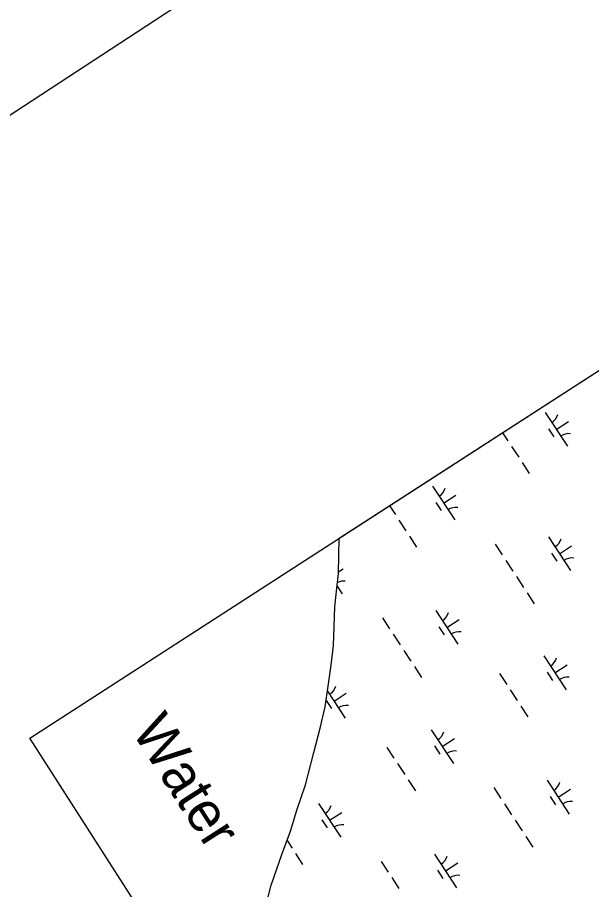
# Model space of a CAD drawing. Extents: x 3945642 to 3966284, y 206476 to 228921.
# Drawn here: x 3949497 to 3950206, y 221813 to 222891 of the extents above; entities that cross this region are included whole.
import ezdxf

# ---------------------------------------------------------------- set-up
doc = ezdxf.new("R2010")
doc.units = 0
for name, color, linetype in [('V-ANNO-SYMB', 7, 'Continuous'), ('V-GRID-FRAM', 7, 'Continuous'), ('V-RIVR-IDEN', 7, 'Continuous'), ('V-TOPO-SHOR', 7, 'Continuous'), ('V-WETL-SWMP', 7, 'Continuous')]:
    doc.layers.add(name, color=color, linetype=linetype)

msp = doc.modelspace()

# ---------------------------------------------------------------- linework, layer by layer
at = {"layer": 'V-ANNO-SYMB'}
msp.add_lwpolyline([(3946901.3, 221076.1), (3955966, 207239.3), (3965550.7, 213518.4), (3956486, 227355.2), (3946901.3, 221076.1)], dxfattribs=at)
at = {"layer": 'V-GRID-FRAM'}
msp.add_lwpolyline([(3956475, 226502.1), (3964764.2, 213849), (3957669.1, 209282.6), (3949512, 222000.5), (3956475, 226502.1)], dxfattribs=at)
at = {"layer": 'V-TOPO-SHOR'}
msp.add_lwpolyline([(3949756.7, 221619.1), (3949761.5, 221632.2), (3949773.3, 221669.4), (3949781.4, 221704.3), (3949790.5, 221741.6), (3949810.1, 221818.6), (3949823.1, 221856.7), (3949834.1, 221885.6), (3949842, 221911.4), (3949852.3, 221942.6), (3949862.9, 221982.7), (3949870.6, 222012.9), (3949876.7, 222039.2), (3949880.7, 222064.7), (3949884.4, 222090.5), (3949886.9, 222114.9), (3949888, 222138.6), (3949888.9, 222162.8), (3949891.4, 222185.7), (3949893.4, 222203.9), (3949894.2, 222247.6)], dxfattribs=at)
at = {"layer": 'V-WETL-SWMP'}
for p, q in [((3949894.2, 222247.6), (3951367.7, 223200.2)), ((3950148.5, 222403.1), (3950175.9, 222361.3)), ((3950152.5, 222383), (3950159.1, 222373)), ((3950162.2, 222382.2), (3950177.3, 222392.1)), ((3950096, 222378), (3950102.6, 222367.9)), ((3950107, 222361.2), (3950115.8, 222347.8)), ((3950120.1, 222341.2), (3950128.9, 222327.8)), ((3950009.4, 222312), (3950036.8, 222270.2)), ((3950023.1, 222291.1), (3950038.1, 222300.9)), ((3949956.3, 222287.7), (3949963.5, 222276.8)), ((3950013.3, 222291.9), (3950019.9, 222281.8)), ((3949967.9, 222270.1), (3949976.6, 222256.7)), ((3949893.4, 222203.9), (3949894.2, 222247.6)), ((3949981, 222250), (3949989.8, 222236.6)), ((3950152.5, 222249.4), (3950179.9, 222207.6)), ((3950086.7, 222240.3), (3950095.4, 222226.9)), ((3950166.2, 222228.5), (3950181.2, 222238.4)), ((3950156.4, 222229.3), (3950163, 222219.3)), ((3950099.8, 222220.2), (3950108.6, 222206.9)), ((3949891.4, 222185.7), (3949893.4, 222203.9)), ((3949893.4, 222206.1), (3949899, 222209.8)), ((3950113, 222200.2), (3950121.7, 222186.8)), ((3949888.9, 222162.8), (3949891.4, 222185.7)), ((3949891.7, 222188.2), (3949897.7, 222179)), ((3950126.1, 222180.1), (3950134.9, 222166.7)), ((3949888, 222138.6), (3949888.9, 222162.8)), ((3950013.3, 222158.3), (3950040.7, 222116.5)), ((3949947.5, 222149.2), (3949956.3, 222135.8)), ((3950027, 222137.4), (3950042.1, 222147.2)), ((3949886.9, 222114.9), (3949888, 222138.6)), ((3950017.3, 222138.2), (3950023.9, 222128.1)), ((3949960.7, 222129.1), (3949969.5, 222115.7)), ((3949884.4, 222090.5), (3949886.9, 222114.9)), ((3949973.8, 222109), (3949982.6, 222095.6)), ((3950146.9, 222102.1), (3950174.3, 222060.2)), ((3949880.7, 222064.7), (3949884.4, 222090.5)), ((3949987, 222088.9), (3949995.8, 222075.6)), ((3950150.9, 222081.9), (3950157.4, 222071.9)), ((3950160.6, 222081.2), (3950175.7, 222091)), ((3950092.2, 222080.2), (3950101, 222066.8)), ((3949876.7, 222039.2), (3949880.7, 222064.7)), ((3950105.4, 222060.2), (3950114.1, 222046.8)), ((3949879.7, 222058.7), (3949901.6, 222025.3)), ((3949887.9, 222046.2), (3949902.9, 222056.1)), ((3949870.6, 222012.9), (3949876.7, 222039.2)), ((3949878.1, 222047), (3949884.7, 222037)), ((3950118.5, 222040.1), (3950127.3, 222026.7)), ((3949862.9, 221982.7), (3949870.6, 222012.9)), ((3950007.8, 222010.9), (3950035.2, 221969.1)), ((3950021.5, 221990), (3950036.5, 221999.9)), ((3949953.1, 221989.1), (3949961.8, 221975.7)), ((3950011.7, 221990.8), (3950018.3, 221980.8)), ((3949852.3, 221942.6), (3949862.9, 221982.7)), ((3949966.2, 221969), (3949975, 221955.6)), ((3949842, 221911.4), (3949852.3, 221942.6)), ((3949979.4, 221948.9), (3949988.2, 221935.5)), ((3950150.8, 221948.4), (3950178.2, 221906.6)), ((3950085.1, 221939.3), (3950093.8, 221925.9)), ((3950164.5, 221927.5), (3950179.6, 221937.3)), ((3949868.6, 221919.8), (3949896, 221877.9)), ((3950098.2, 221919.2), (3950107, 221905.8)), ((3950154.8, 221928.3), (3950161.4, 221918.2)), ((3949834.1, 221885.6), (3949842, 221911.4)), ((3949882.3, 221898.9), (3949897.4, 221908.7)), ((3949872.6, 221899.6), (3949879.2, 221889.6)), ((3950111.4, 221899.1), (3950120.1, 221885.7)), ((3949823.1, 221856.7), (3949834.1, 221885.6)), ((3950124.5, 221879), (3950133.3, 221865.6)), ((3949829.7, 221873.9), (3949835.9, 221864.5)), ((3949810.1, 221818.6), (3949823.1, 221856.7)), ((3949840.2, 221857.8), (3949849, 221844.4)), ((3950011.7, 221857.2), (3950039.1, 221815.4)), ((3949945.9, 221848.1), (3949954.7, 221834.7)), ((3950025.4, 221836.3), (3950040.5, 221846.2)), ((3950015.7, 221837.1), (3950022.2, 221827.1)), ((3949959.1, 221828), (3949967.8, 221814.6)), ((3949790.5, 221741.6), (3949810.1, 221818.6))]:
    msp.add_line(p, q, dxfattribs=at)
for centre, start, end in [((3950147.3, 222405.5), 302.4575, 344.0011), ((3950177.6, 222359.3), 82.4574, 124.0011), ((3950008.2, 222314.3), 302.4575, 344.0011), ((3950038.4, 222268.1), 82.4574, 124.0011), ((3950151.2, 222251.8), 302.4575, 344.0011), ((3950181.5, 222205.6), 82.4574, 124.0011), ((3949899.3, 222176.9), 82.4574, 113.7385), ((3950012.1, 222160.6), 302.4575, 344.0011), ((3950042.4, 222114.4), 82.4574, 124.0011), ((3950145.7, 222104.4), 302.4575, 344.0011), ((3950175.9, 222058.2), 82.4574, 124.0011), ((3949872.9, 222069.5), 302.4575, 344.0011), ((3949903.2, 222023.3), 82.4574, 124.0011), ((3950006.5, 222013.2), 302.4575, 344.0011), ((3950036.8, 221967), 82.4574, 124.0011), ((3950149.6, 221950.7), 302.4575, 344.0011), ((3950179.9, 221904.5), 82.4574, 124.0011), ((3949867.4, 221922.1), 302.4575, 344.0011), ((3949897.7, 221875.9), 82.4574, 124.0011), ((3950010.5, 221859.5), 302.4575, 344.0011), ((3950040.7, 221813.3), 82.4574, 124.0011)]:
    msp.add_arc(centre, 17.6, start, end, dxfattribs=at)

# ---------------------------------------------------------------- texts
at = {"layer": 'V-RIVR-IDEN'}
msp.add_text('Water', height=50, rotation=302.6757, dxfattribs=at).set_placement((3949636.8, 222009.5))

doc.saveas('drawing.dxf')
